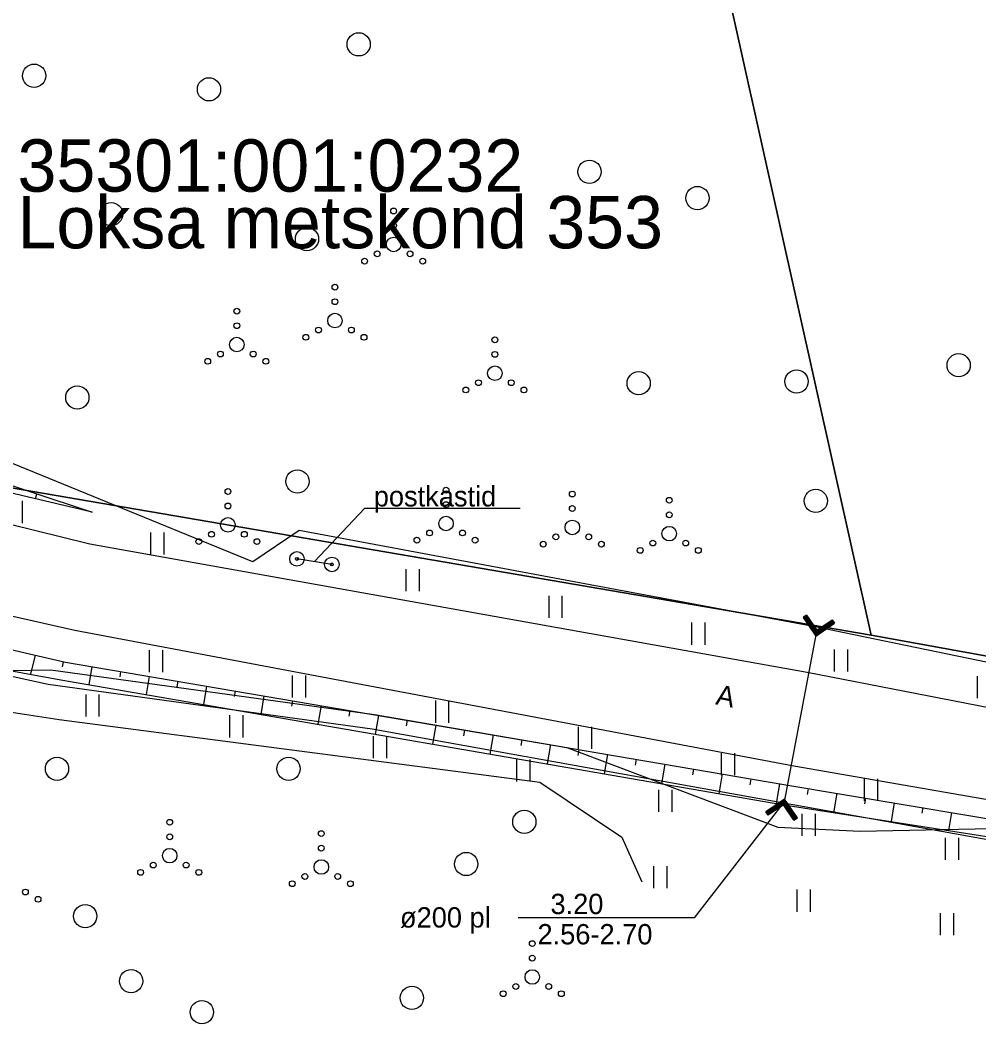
# Model space of a CAD drawing. Extents: x 599446 to 599962, y 6608194 to 6608886.
# Drawn here: x 599799.45 to 599832.44, y 6608574.6 to 6608609.15 of the extents above; entities that cross this region are included whole.
import ezdxf

# ---------------------------------------------------------------- set-up
doc = ezdxf.new("R2010")
doc.units = 0
for name, color, linetype in [('HALJASTUS', 7, 'Continuous'), ('LIIKLUS', 7, 'Continuous'), ('MPKAABEL', 7, 'Continuous'), ('PIIR', 7, 'Continuous'), ('PR_SIDE', 7, 'Continuous'), ('RELJEEF', 7, 'Continuous'), ('TEE', 7, 'Continuous'), ('TRUUP', 7, 'Continuous')]:
    doc.layers.add(name, color=color, linetype=linetype)

msp = doc.modelspace()

# ---------------------------------------------------------------- linework, layer by layer
at = {"layer": 'HALJASTUS'}
for p, q in [((599799.512, 6608592.6), (599799.512, 6608591.839)), ((599803.938, 6608591.515), (599803.938, 6608590.753)), ((599804.393, 6608591.515), (599804.393, 6608590.753)), ((599812.721, 6608590.257), (599812.721, 6608589.496)), ((599813.176, 6608590.257), (599813.176, 6608589.496)), ((599817.635, 6608589.335), (599817.635, 6608588.574)), ((599818.09, 6608589.335), (599818.09, 6608588.574)), ((599822.549, 6608588.413), (599822.549, 6608587.652)), ((599823.004, 6608588.413), (599823.004, 6608587.652)), ((599827.464, 6608587.491), (599827.464, 6608586.73)), ((599827.919, 6608587.491), (599827.919, 6608586.73)), ((599803.887, 6608587.464), (599803.887, 6608586.703)), ((599804.342, 6608587.464), (599804.342, 6608586.703)), ((599808.811, 6608586.595), (599808.811, 6608585.834)), ((599809.266, 6608586.595), (599809.266, 6608585.834)), ((599832.378, 6608586.569), (599832.378, 6608585.808)), ((599801.703, 6608585.942), (599801.703, 6608585.181)), ((599802.158, 6608585.942), (599802.158, 6608585.181)), ((599813.735, 6608585.726), (599813.735, 6608584.965)), ((599814.19, 6608585.726), (599814.19, 6608584.965)), ((599806.651, 6608585.224), (599806.651, 6608584.462)), ((599807.107, 6608585.224), (599807.107, 6608584.462)), ((599818.653, 6608584.826), (599818.653, 6608584.064)), ((599819.108, 6608584.826), (599819.108, 6608584.064)), ((599811.6, 6608584.505), (599811.6, 6608583.744)), ((599812.055, 6608584.505), (599812.055, 6608583.744)), ((599816.531, 6608583.702), (599816.531, 6608582.941)), ((599816.986, 6608583.702), (599816.986, 6608582.941)), ((599823.57, 6608583.918), (599823.57, 6608583.157)), ((599824.025, 6608583.918), (599824.025, 6608583.157)), ((599828.492, 6608583.039), (599828.492, 6608582.277)), ((599828.947, 6608583.039), (599828.947, 6608582.277)), ((599821.418, 6608582.656), (599821.418, 6608581.894)), ((599821.873, 6608582.656), (599821.873, 6608581.894)), ((599826.349, 6608581.83), (599826.349, 6608581.069)), ((599826.804, 6608581.83), (599826.804, 6608581.069)), ((599831.281, 6608581.005), (599831.281, 6608580.244)), ((599831.736, 6608581.005), (599831.736, 6608580.244)), ((599821.24, 6608580.029), (599821.24, 6608579.268)), ((599821.695, 6608580.029), (599821.695, 6608579.268)), ((599826.175, 6608579.221), (599826.175, 6608578.46)), ((599826.63, 6608579.221), (599826.63, 6608578.46)), ((599831.109, 6608578.413), (599831.109, 6608577.652)), ((599831.564, 6608578.413), (599831.564, 6608577.652))]:
    msp.add_line(p, q, dxfattribs=at)
for points in [[(599854.437, 6608582.858), (599845.632, 6608584.378), (599826.804, 6608588.268), (599809.044, 6608591.586), (599807.451, 6608590.502), (599796.451, 6608594.999), (599793.207, 6608594.269), (599791.661, 6608599.006), (599795.433, 6608607.227), (599809.992, 6608629.503), (599824.333, 6608648.974), (599834.941, 6608664.558), (599840.035, 6608665.745), (599843.227, 6608674.906), (599844.956, 6608681.949), (599852.543, 6608691.108)], [(599745.503, 6608533.608), (599751.758, 6608542.414), (599769.125, 6608566.517), (599781.306, 6608584.539), (599784.695, 6608586.729), (599788.555, 6608586.954), (599800.791, 6608585.081), (599817.331, 6608582.921), (599820.151, 6608581.025), (599820.842, 6608579.488)]]:
    msp.add_lwpolyline(points, dxfattribs=at)
for centre, radius in [((599811.097, 6608608.317), 0.4), ((599799.929, 6608607.238), 0.4), ((599805.945, 6608606.769), 0.4), ((599819.039, 6608603.932), 0.4), ((599822.754, 6608603.027), 0.4), ((599802.576, 6608602.475), 0.4), ((599812.3, 6608602.581), 0.1), ((599809.318, 6608601.614), 0.4), ((599812.3, 6608602.081), 0.1), ((599812.3, 6608601.431), 0.25), ((599811.3, 6608600.856), 0.1), ((599811.735, 6608601.106), 0.1), ((599812.865, 6608601.106), 0.1), ((599813.3, 6608600.856), 0.1), ((599810.28, 6608599.959), 0.1), ((599806.903, 6608599.133), 0.1), ((599810.28, 6608599.459), 0.1), ((599810.28, 6608598.809), 0.25), ((599806.903, 6608598.633), 0.1), ((599809.715, 6608598.484), 0.1), ((599810.845, 6608598.484), 0.1), ((599806.903, 6608597.983), 0.25), ((599809.28, 6608598.234), 0.1), ((599811.28, 6608598.234), 0.1), ((599815.784, 6608598.146), 0.1), ((599805.903, 6608597.408), 0.1), ((599806.338, 6608597.658), 0.1), ((599807.468, 6608597.658), 0.1), ((599807.903, 6608597.408), 0.1), ((599815.784, 6608597.646), 0.1), ((599831.741, 6608597.271), 0.4), ((599815.784, 6608596.996), 0.25), ((599820.731, 6608596.652), 0.4), ((599826.165, 6608596.712), 0.4), ((599801.415, 6608596.162), 0.4), ((599814.784, 6608596.421), 0.1), ((599815.219, 6608596.671), 0.1), ((599816.349, 6608596.671), 0.1), ((599816.784, 6608596.421), 0.1), ((599808.988, 6608593.274), 0.4), ((599806.597, 6608592.927), 0.1), ((599814.103, 6608592.974), 0.1), ((599826.824, 6608592.602), 0.4), ((599818.448, 6608592.839), 0.1), ((599821.784, 6608592.625), 0.1), ((599806.597, 6608592.427), 0.1), ((599814.103, 6608592.474), 0.1), ((599818.448, 6608592.339), 0.1), ((599806.597, 6608591.777), 0.25), ((599814.103, 6608591.824), 0.25), ((599821.784, 6608592.125), 0.1), ((599818.448, 6608591.689), 0.25), ((599821.784, 6608591.475), 0.25), ((599805.597, 6608591.202), 0.1), ((599806.032, 6608591.452), 0.1), ((599807.162, 6608591.452), 0.1), ((599807.597, 6608591.202), 0.1), ((599813.103, 6608591.249), 0.1), ((599813.538, 6608591.499), 0.1), ((599814.668, 6608591.499), 0.1), ((599815.103, 6608591.249), 0.1), ((599817.883, 6608591.364), 0.1), ((599819.013, 6608591.364), 0.1), ((599817.448, 6608591.114), 0.1), ((599819.448, 6608591.114), 0.1), ((599820.784, 6608590.9), 0.1), ((599821.219, 6608591.15), 0.1), ((599822.349, 6608591.15), 0.1), ((599822.784, 6608590.9), 0.1), ((599800.716, 6608583.381), 0.4), ((599808.684, 6608583.381), 0.4), ((599816.797, 6608581.555), 0.4), ((599804.594, 6608581.541), 0.1), ((599804.594, 6608581.041), 0.1), ((599809.811, 6608581.15), 0.1), ((599804.594, 6608580.391), 0.25), ((599809.811, 6608580.65), 0.1), ((599809.811, 6608580), 0.25), ((599814.797, 6608580.103), 0.4), ((599803.594, 6608579.816), 0.1), ((599804.029, 6608580.066), 0.1), ((599805.159, 6608580.066), 0.1), ((599805.594, 6608579.816), 0.1), ((599808.811, 6608579.425), 0.1), ((599809.246, 6608579.675), 0.1), ((599810.376, 6608579.675), 0.1), ((599810.811, 6608579.425), 0.1), ((599799.628, 6608579.139), 0.1), ((599800.063, 6608578.889), 0.1), ((599801.687, 6608578.308), 0.4), ((599817.07, 6608577.364), 0.1), ((599817.07, 6608576.864), 0.1), ((599803.267, 6608576.074), 0.4), ((599817.07, 6608576.214), 0.25), ((599812.927, 6608575.493), 0.4), ((599816.07, 6608575.639), 0.1), ((599816.505, 6608575.889), 0.1), ((599817.635, 6608575.889), 0.1), ((599818.07, 6608575.639), 0.1), ((599805.702, 6608575.004), 0.4)]:
    msp.add_circle(centre, radius, dxfattribs=at)
at = {"layer": 'LIIKLUS'}
msp.add_line((599810.174, 6608590.416), (599808.972, 6608590.606), dxfattribs=at)
msp.add_lwpolyline([(599816.653, 6608592.344), (599811.301, 6608592.344), (599809.573, 6608590.511)], dxfattribs=at)
for centre, radius in [((599808.972, 6608590.606), 0.25), ((599808.972, 6608590.606), 0.05), ((599810.174, 6608590.416), 0.25), ((599810.174, 6608590.416), 0.05)]:
    msp.add_circle(centre, radius, dxfattribs=at)
at = {"layer": 'MPKAABEL'}
msp.add_lwpolyline([(599782.282, 6608586.259), (599782.405, 6608586.985), (599783.936, 6608589.015), (599789.503, 6608588.678), (599800.41, 6608586.298), (599811.564, 6608584.757), (599822.594, 6608582.77), (599833.067, 6608580.884), (599844.238, 6608579.354), (599854.437, 6608577.709)], dxfattribs=at)
at = {"layer": 'PIIR'}
for points in [[(599854.437, 6608583.323), (599828.73, 6608587.98), (599817.31, 6608639.31), (599851.222, 6608691.108)], [(599746.81, 6608533.608), (599788.83, 6608594.82), (599828.73, 6608587.98), (599854.437, 6608583.323)]]:
    msp.add_lwpolyline(points, dxfattribs=at)
msp.add_lwpolyline([(599817.31, 6608639.31), (599828.73, 6608587.98), (599788.83, 6608594.82)], close=True, dxfattribs=at)
at = {"layer": 'PR_SIDE'}
msp.add_lwpolyline([(599780.528, 6608585.299), (599782.442, 6608587.336), (599785.44, 6608588.423), (599789.434, 6608588.181), (599795.884, 6608586.707), (599800.498, 6608586.791), (599811.643, 6608585.251), (599818.26, 6608584.116), (599825.524, 6608581.372), (599828.353, 6608581.236), (599833.433, 6608581.339), (599844.541, 6608579.758), (599850.447, 6608578.807), (599854.437, 6608578.085)], dxfattribs=at)
at = {"layer": 'RELJEEF'}
for p, q in [((599799.98, 6608592.672), (599800.02, 6608592.844)), ((599800.953, 6608592.442), (599800.959, 6608592.468)), ((599799.959, 6608587.293), (599799.807, 6608586.637)), ((599800.933, 6608587.068), (599800.891, 6608586.885)), ((599801.918, 6608586.896), (599801.813, 6608586.28)), ((599802.904, 6608586.728), (599802.873, 6608586.543)), ((599803.89, 6608586.561), (599803.784, 6608585.938)), ((599804.876, 6608586.393), (599804.844, 6608586.205)), ((599805.862, 6608586.225), (599805.755, 6608585.597)), ((599806.847, 6608586.057), (599806.815, 6608585.868)), ((599807.833, 6608585.89), (599807.725, 6608585.255)), ((599808.819, 6608585.722), (599808.787, 6608585.531)), ((599809.805, 6608585.554), (599809.696, 6608584.913)), ((599810.791, 6608585.386), (599810.758, 6608585.193)), ((599811.777, 6608585.219), (599811.667, 6608584.572)), ((599812.762, 6608585.051), (599812.729, 6608584.856)), ((599813.748, 6608584.883), (599813.637, 6608584.23)), ((599814.734, 6608584.715), (599814.701, 6608584.519)), ((599815.72, 6608584.548), (599815.608, 6608583.888)), ((599816.706, 6608584.38), (599816.672, 6608584.181)), ((599817.692, 6608584.212), (599817.578, 6608583.547)), ((599818.677, 6608584.044), (599818.643, 6608583.844)), ((599819.663, 6608583.877), (599819.549, 6608583.205)), ((599820.649, 6608583.709), (599820.615, 6608583.507)), ((599821.635, 6608583.541), (599821.52, 6608582.863)), ((599822.621, 6608583.373), (599822.586, 6608583.169)), ((599823.607, 6608583.206), (599823.49, 6608582.522)), ((599824.592, 6608583.038), (599824.557, 6608582.832)), ((599825.578, 6608582.87), (599825.461, 6608582.18)), ((599826.564, 6608582.705), (599826.53, 6608582.5)), ((599827.551, 6608582.539), (599827.438, 6608581.87)), ((599828.537, 6608582.374), (599828.504, 6608582.177)), ((599829.523, 6608582.209), (599829.415, 6608581.563)), ((599830.509, 6608582.043), (599830.478, 6608581.853)), ((599831.496, 6608581.878), (599831.391, 6608581.256))]:
    msp.add_line(p, q, dxfattribs=at)
for points in [[(599801.926, 6608592.213), (599793.207, 6608594.269), (599789.122, 6608596.036), (599787.113, 6608597.941), (599787.676, 6608601.107), (599788.191, 6608604.386), (599791.963, 6608612.218), (599804.959, 6608633.141), (599818.082, 6608652.827), (599831.188, 6608665.923), (599841.493, 6608683.919), (599846.39, 6608691.108)], [(599850.124, 6608691.108), (599843.352, 6608682.219), (599833.329, 6608665.805), (599822.288, 6608650.45), (599809.505, 6608629.745), (599794.311, 6608608.062), (599789.813, 6608601.009), (599790.211, 6608598.052), (599793.476, 6608595.009), (599801.926, 6608592.213)], [(599738.503, 6608533.608), (599747.576, 6608546.588), (599763.358, 6608570.259), (599776.504, 6608588.973), (599778.685, 6608590.228), (599780.974, 6608590.85), (599782.591, 6608590.668), (599789.068, 6608589.811), (599801.004, 6608587.052), (599825.729, 6608582.845), (599838.459, 6608580.711), (599854.437, 6608577.458)], [(599743.905, 6608533.608), (599750.951, 6608543.213), (599767.627, 6608567.644), (599779.48, 6608586.231), (599782.154, 6608588.41), (599783.352, 6608588.883), (599788.843, 6608588.633), (599800.848, 6608586.447), (599825.652, 6608582.147), (599838.441, 6608580.161), (599854.437, 6608577.335)]]:
    msp.add_lwpolyline(points, dxfattribs=at)
at = {"layer": 'TEE'}
for points in [[(599854.437, 6608581.395), (599845.399, 6608583.02), (599826.526, 6608586.694), (599801.842, 6608591.113), (599789.613, 6608594.125), (599786.413, 6608596.947), (599784.756, 6608598.98), (599784.301, 6608601.825), (599784.669, 6608604.283), (599790.786, 6608613.879), (599804.071, 6608634.135), (599817.047, 6608653.619), (599838.859, 6608686.624), (599841.837, 6608691.108)], [(599854.437, 6608578.651), (599844.624, 6608580.251), (599826.075, 6608583.474), (599801.334, 6608588.138), (599788.813, 6608590.962), (599783.359, 6608592.522), (599779.225, 6608592.079), (599775.664, 6608590.875), (599762.015, 6608571.264), (599745.769, 6608547.626), (599736.468, 6608533.608)]]:
    msp.add_lwpolyline(points, dxfattribs=at)
at = {"layer": 'TRUUP'}
for p, q in [((599826.505, 6608588.674), (599826.387, 6608588.594)), ((599826.387, 6608588.594), (599826.825, 6608587.951)), ((599826.412, 6608588.611), (599826.42, 6608588.546)), ((599826.435, 6608588.626), (599826.451, 6608588.5)), ((599826.446, 6608588.634), (599826.844, 6608588.049)), ((599826.458, 6608588.642), (599826.483, 6608588.454)), ((599826.481, 6608588.658), (599826.514, 6608588.408)), ((599826.504, 6608588.674), (599826.545, 6608588.362)), ((599826.505, 6608588.674), (599826.863, 6608588.148)), ((599826.535, 6608588.63), (599826.576, 6608588.316)), ((599826.566, 6608588.584), (599826.608, 6608588.27)), ((599826.598, 6608588.538), (599826.639, 6608588.224)), ((599826.629, 6608588.492), (599826.67, 6608588.178)), ((599826.66, 6608588.446), (599826.701, 6608588.132)), ((599826.691, 6608588.4), (599826.733, 6608588.087)), ((599826.723, 6608588.354), (599826.764, 6608588.041)), ((599826.754, 6608588.308), (599826.795, 6608587.995)), ((599826.785, 6608588.262), (599826.826, 6608587.951)), ((599826.816, 6608588.216), (599826.849, 6608587.967)), ((599826.825, 6608587.951), (599827.469, 6608588.388)), ((599826.844, 6608588.049), (599827.429, 6608588.447)), ((599826.848, 6608588.17), (599826.872, 6608587.983)), ((599826.863, 6608588.148), (599827.389, 6608588.506)), ((599826.898, 6608588.172), (599826.918, 6608588.014)), ((599826.921, 6608588.188), (599826.942, 6608588.03)), ((599826.944, 6608588.204), (599826.965, 6608588.046)), ((599826.967, 6608588.219), (599826.988, 6608588.061)), ((599826.99, 6608588.235), (599827.011, 6608588.077)), ((599827.014, 6608588.251), (599827.034, 6608588.093)), ((599827.037, 6608588.267), (599827.057, 6608588.109)), ((599827.06, 6608588.282), (599827.081, 6608588.124)), ((599827.083, 6608588.298), (599827.104, 6608588.14)), ((599827.106, 6608588.314), (599827.127, 6608588.156)), ((599827.129, 6608588.33), (599827.15, 6608588.171)), ((599827.152, 6608588.345), (599827.173, 6608588.187)), ((599827.176, 6608588.361), (599827.196, 6608588.203)), ((599827.199, 6608588.377), (599827.219, 6608588.219)), ((599827.222, 6608588.392), (599827.243, 6608588.234)), ((599827.245, 6608588.408), (599827.266, 6608588.25)), ((599827.268, 6608588.424), (599827.289, 6608588.266)), ((599827.291, 6608588.44), (599827.312, 6608588.282)), ((599827.315, 6608588.455), (599827.335, 6608588.297)), ((599827.338, 6608588.471), (599827.358, 6608588.313)), ((599827.361, 6608588.487), (599827.382, 6608588.329)), ((599827.384, 6608588.503), (599827.405, 6608588.345)), ((599827.389, 6608588.506), (599827.469, 6608588.388)), ((599827.414, 6608588.469), (599827.428, 6608588.36)), ((599827.445, 6608588.423), (599827.451, 6608588.376)), ((599826.844, 6608588.049), (599825.736, 6608582.242)), ((599826.875, 6608588.156), (599826.895, 6608587.998)), ((599825.755, 6608582.34), (599825.112, 6608581.903)), ((599825.706, 6608582.135), (599825.685, 6608582.293)), ((599825.733, 6608582.121), (599825.708, 6608582.308)), ((599825.764, 6608582.075), (599825.731, 6608582.324)), ((599825.795, 6608582.029), (599825.754, 6608582.34)), ((599826.193, 6608581.697), (599825.755, 6608582.34)), ((599825.826, 6608581.983), (599825.785, 6608582.296)), ((599825.736, 6608582.242), (599825.152, 6608581.844)), ((599825.196, 6608581.788), (599825.176, 6608581.946)), ((599825.718, 6608582.143), (599825.192, 6608581.785)), ((599825.219, 6608581.804), (599825.199, 6608581.962)), ((599825.243, 6608581.82), (599825.222, 6608581.978)), ((599825.266, 6608581.836), (599825.245, 6608581.994)), ((599825.289, 6608581.851), (599825.268, 6608582.009)), ((599825.312, 6608581.867), (599825.291, 6608582.025)), ((599825.335, 6608581.883), (599825.315, 6608582.041)), ((599825.358, 6608581.899), (599825.338, 6608582.057)), ((599825.382, 6608581.914), (599825.361, 6608582.072)), ((599825.405, 6608581.93), (599825.384, 6608582.088)), ((599825.428, 6608581.946), (599825.407, 6608582.104)), ((599825.451, 6608581.961), (599825.43, 6608582.12)), ((599825.474, 6608581.977), (599825.453, 6608582.135)), ((599825.497, 6608581.993), (599825.477, 6608582.151)), ((599825.52, 6608582.009), (599825.5, 6608582.167)), ((599825.544, 6608582.024), (599825.523, 6608582.182)), ((599825.567, 6608582.04), (599825.546, 6608582.198)), ((599825.59, 6608582.056), (599825.569, 6608582.214)), ((599825.613, 6608582.072), (599825.592, 6608582.23)), ((599825.636, 6608582.087), (599825.616, 6608582.245)), ((599825.659, 6608582.103), (599825.639, 6608582.261)), ((599825.683, 6608582.119), (599825.662, 6608582.277)), ((599826.075, 6608581.617), (599825.718, 6608582.143)), ((599826.134, 6608581.657), (599825.736, 6608582.242)), ((599825.858, 6608581.937), (599825.817, 6608582.25)), ((599825.889, 6608581.891), (599825.848, 6608582.204)), ((599825.92, 6608581.845), (599825.879, 6608582.159)), ((599825.951, 6608581.799), (599825.91, 6608582.113)), ((599825.983, 6608581.753), (599825.941, 6608582.067)), ((599826.014, 6608581.707), (599825.973, 6608582.021)), ((599826.045, 6608581.661), (599826.004, 6608581.975)), ((599825.192, 6608581.785), (599825.112, 6608581.903)), ((599825.135, 6608581.868), (599825.129, 6608581.915)), ((599825.167, 6608581.822), (599825.152, 6608581.931)), ((599826.076, 6608581.617), (599826.035, 6608581.929)), ((599826.099, 6608581.633), (599826.066, 6608581.883)), ((599826.075, 6608581.617), (599826.193, 6608581.697)), ((599826.122, 6608581.649), (599826.098, 6608581.837)), ((599826.145, 6608581.665), (599826.129, 6608581.791)), ((599826.169, 6608581.68), (599826.16, 6608581.745))]:
    msp.add_line(p, q, dxfattribs=at)
msp.add_lwpolyline([(599825.736, 6608582.242), (599822.639, 6608578.252), (599816.581, 6608578.252)], dxfattribs=at)

# ---------------------------------------------------------------- texts
at = {"layer": 'LIIKLUS'}
msp.add_text('postkastid', height=0.7, dxfattribs=at).set_placement((599811.616, 6608592.411))
at = {"layer": 'PIIR'}
for s, p in [('35301:001:0232', (599799.357, 6608603.247)), ('Loksa metskond 353', (599799.357, 6608601.297))]:
    msp.add_text(s, height=1.8, dxfattribs=at).set_placement(p)
at = {"layer": 'TEE'}
msp.add_text('A', height=0.7, rotation=348.8245, dxfattribs=at).set_placement((599823.354, 6608585.604))
at = {"layer": 'TRUUP'}
for s, p in [('3.20', (599817.696, 6608578.379)), ('ø200 pl', (599812.518, 6608577.916)), ('2.56-2.70', (599817.25, 6608577.337))]:
    msp.add_text(s, height=0.7, dxfattribs=at).set_placement(p)

doc.saveas('drawing.dxf')
